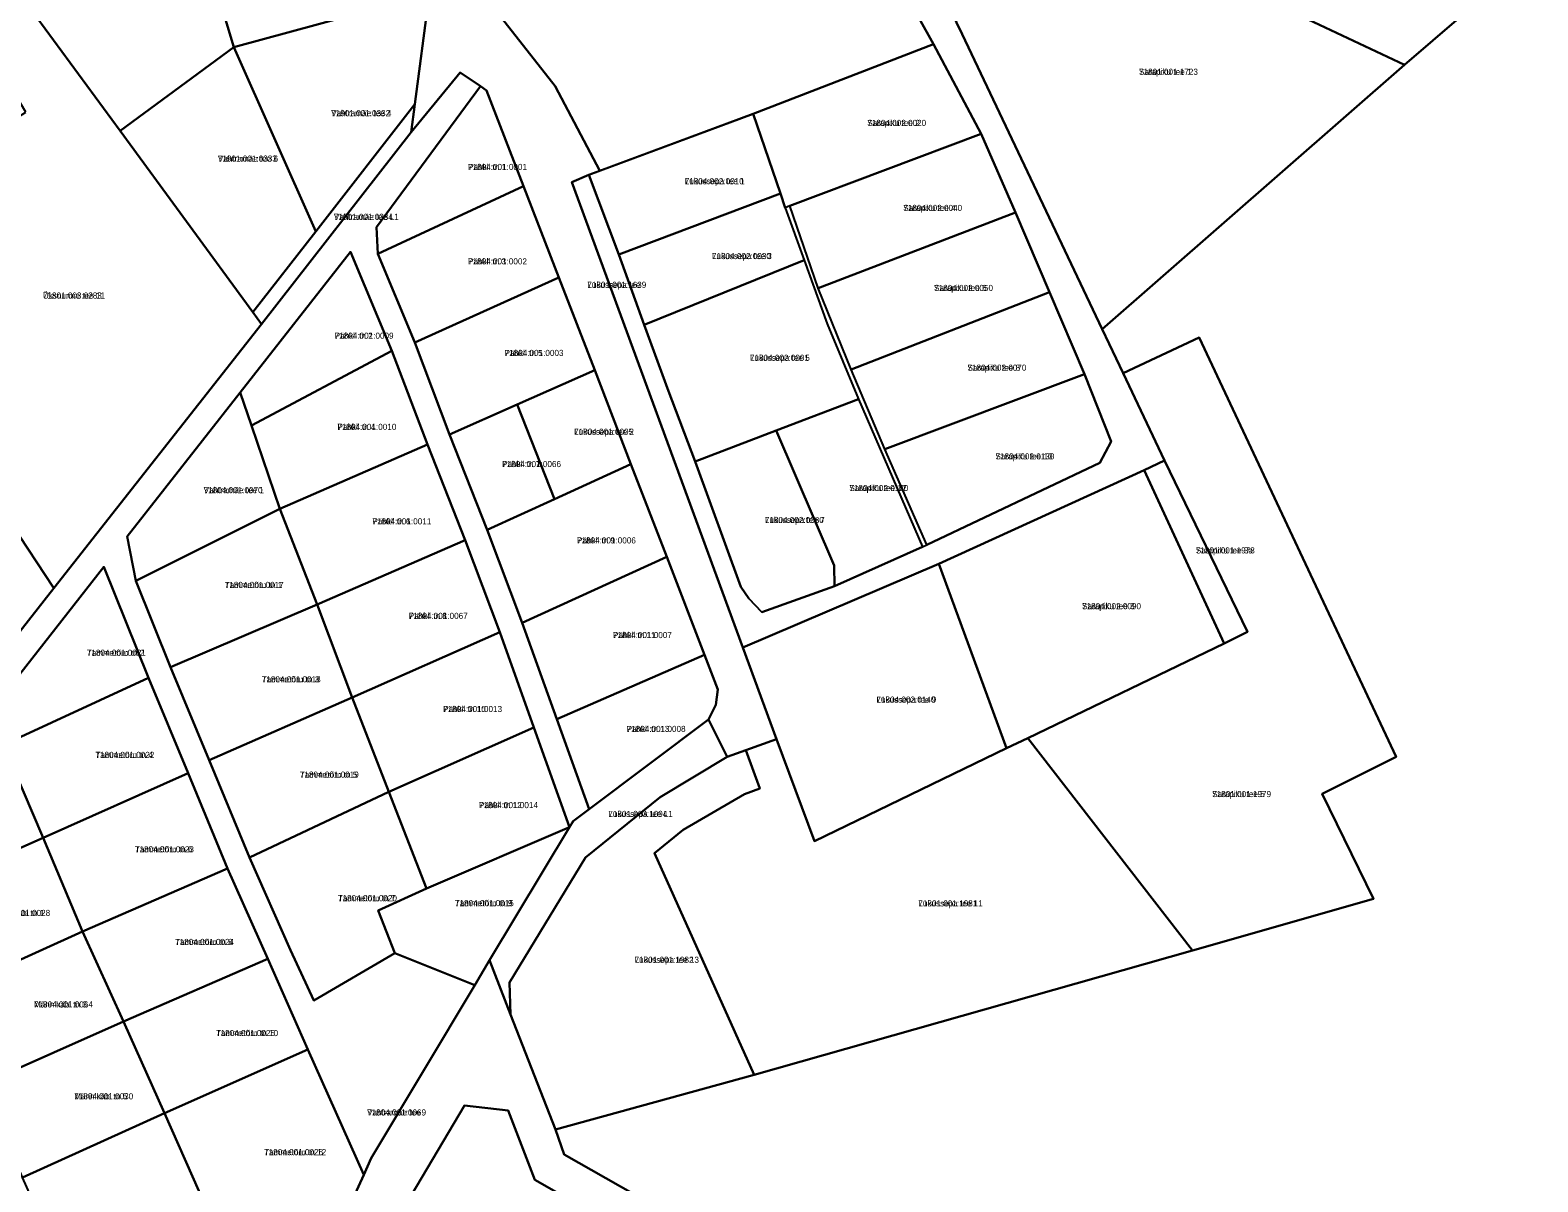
# Model space of a CAD drawing. Extents: x 529768 to 552006, y 6562269 to 6580975.
# Drawn here: x 536836 to 537206.9, y 6572299.8 to 6572583.3 of the extents above; entities that cross this region are included whole.
import ezdxf

# ---------------------------------------------------------------- set-up
doc = ezdxf.new("R2010")
doc.units = 0
for name, color, linetype in [('L_AADRESS', 7, 'Continuous'), ('PIIR', 7, 'Continuous'), ('TUNNUS', 7, 'Continuous')]:
    doc.layers.add(name, color=color, linetype=linetype)

msp = doc.modelspace()

# ---------------------------------------------------------------- linework, layer by layer
at = {"layer": 'PIIR'}
for points in [[(536949.22, 6572589.75), (536938.38, 6572627.92), (537020.07, 6572648.36), (537058.21, 6572579.8), (537013.87, 6572562.67), (536976.18, 6572548.65), (536965.17, 6572569.51)], [(537065.26, 6572582.3), (537043.48, 6572627.3), (537100.97, 6572644.38), (537109.91, 6572624.44), (537110.31, 6572623.51), (537120.04, 6572600.67), (537142.03, 6572589.8), (537174.13, 6572574.71), (537099.76, 6572509.71)], [(537142.03, 6572589.8), (537156.58, 6572600.06), (537198.96, 6572629.82), (537206.08, 6572619.65), (537208.84, 6572621.68), (537216.51, 6572611.21), (537174.13, 6572574.71)], [(536886.08, 6572579.04), (536877.27, 6572608.33), (536922.72, 6572621.78), (536933.5, 6572592.01)], [(536991.51, 6572292.84), (536967.39, 6572306.61), (536965.22, 6572312.7), (537014.09, 6572326.19), (537122.01, 6572356.76), (537166.48, 6572369.47), (537153.91, 6572395.36), (537172.12, 6572404.45), (537123.63, 6572507.61), (537104.93, 6572498.87), (537099.76, 6572509.71), (537174.13, 6572574.71), (537216.51, 6572611.21), (537216.46, 6572545.94), (537216.34, 6572355.99), (537216.73, 6572216.69), (537109.27, 6572167.25), (537012, 6572122.32), (537022.8, 6572262.32), (537006.74, 6572284.07)], [(536858.1, 6572558.51), (536831.48, 6572594.78), (536877.27, 6572608.33), (536886.08, 6572579.04)], [(536834.93, 6572563.1), (536817.36, 6572592.7), (536829.73, 6572597.13), (536831.48, 6572594.78), (536858.1, 6572558.51), (536890.77, 6572513.87), (536892.93, 6572510.9), (536841.8, 6572445.91), (536788.8, 6572526.33), (536785.28, 6572531.79), (536809.39, 6572546.99)], [(536906.23, 6572533.67), (536886.08, 6572579.04), (536933.5, 6572592.01), (536934, 6572590.65), (536930.65, 6572565.02)], [(536890.77, 6572513.87), (536858.1, 6572558.51), (536886.08, 6572579.04), (536906.23, 6572533.67)], [(537021.78, 6572539.56), (537020.56, 6572543.05), (537013.87, 6572562.67), (537058.21, 6572579.8), (537070.01, 6572557.76), (537022.89, 6572540.06)], [(536921.22, 6572534.76), (536946.76, 6572569.48), (536948.29, 6572568.44), (536957.4, 6572544.85), (536921.52, 6572528.19)], [(536892.93, 6572510.9), (536890.77, 6572513.87), (536906.23, 6572533.67), (536930.65, 6572565.02), (536929.76, 6572558.13)], [(536973.45, 6572547.63), (537013.87, 6572562.67), (537020.56, 6572543.05), (536980.78, 6572528.01)], [(537022.89, 6572540.06), (537070.01, 6572557.76), (537078.4, 6572538.42), (537029.86, 6572519.76)], [(536921.52, 6572528.19), (536957.4, 6572544.85), (536966.07, 6572522.39), (536930.63, 6572506.36)], [(536980.78, 6572528.01), (537020.56, 6572543.05), (537021.78, 6572539.56), (537026.4, 6572526.64), (536987.03, 6572510.76)], [(537029.86, 6572519.76), (537078.4, 6572538.42), (537086.76, 6572518.76), (537038.01, 6572499.72)], [(536805.18, 6572414.12), (536790.17, 6572434.86), (536787.8, 6572438.12), (536785.45, 6572441.33), (536744.06, 6572498.45), (536767.58, 6572513.11), (536788.8, 6572526.33), (536841.8, 6572445.91), (536812.33, 6572408.45)], [(536924.99, 6572504.32), (536890.43, 6572485.95), (536887.66, 6572494.07), (536914.8, 6572528.7)], [(536987.03, 6572510.76), (537026.4, 6572526.64), (537032.1, 6572510.95), (537039.8, 6572492.47), (537019.54, 6572484.75), (536999.6, 6572477.11), (536993, 6572494.42)], [(536930.63, 6572506.36), (536966.07, 6572522.39), (536974.88, 6572499.55), (536955.83, 6572491.13), (536939.19, 6572483.77)], [(537038.01, 6572499.72), (537086.76, 6572518.76), (537095.43, 6572498.62), (537046.28, 6572480.13)], [(537122.01, 6572356.76), (537081.48, 6572409.04), (537129.8, 6572432.35), (537135.47, 6572435.19), (537115.09, 6572477.35), (537104.93, 6572498.87), (537123.63, 6572507.61), (537172.12, 6572404.45), (537153.91, 6572395.36), (537166.48, 6572369.47)], [(536933.7, 6572481.32), (536897.43, 6572465.44), (536890.43, 6572485.95), (536924.99, 6572504.32)], [(536974.88, 6572499.55), (536983.81, 6572476.43), (536964.99, 6572467.85), (536955.83, 6572491.13)], [(537046.28, 6572480.13), (537095.43, 6572498.62), (537101.99, 6572482.04), (537099.13, 6572476.81), (537056.59, 6572456.63)], [(536887.66, 6572494.07), (536890.43, 6572485.95), (536897.43, 6572465.44), (536861.97, 6572447.7), (536859.88, 6572458.61)], [(537033.82, 6572451.53), (537019.54, 6572484.75), (537039.8, 6572492.47), (537055.53, 6572456.12), (537033.9, 6572446.43)], [(536939.19, 6572483.77), (536955.83, 6572491.13), (536964.99, 6572467.85), (536948.41, 6572460.3)], [(537010.87, 6572446.3), (536999.6, 6572477.11), (537019.54, 6572484.75), (537033.82, 6572451.53), (537033.9, 6572446.43), (537016.04, 6572440.01), (537012.84, 6572443.42)], [(536942.97, 6572457.73), (536906.6, 6572441.95), (536897.43, 6572465.44), (536933.7, 6572481.32)], [(537129.8, 6572432.35), (537110.1, 6572474.98), (537115.09, 6572477.35), (537135.47, 6572435.19)], [(536948.41, 6572460.3), (536964.99, 6572467.85), (536983.81, 6572476.43), (536992.61, 6572453.63), (536957.07, 6572437.44)], [(537076.24, 6572406.53), (537059.57, 6572451.9), (537110.1, 6572474.98), (537129.8, 6572432.35), (537081.48, 6572409.04)], [(536861.97, 6572447.7), (536897.43, 6572465.44), (536906.6, 6572441.95), (536870.51, 6572426.53)], [(536906.6, 6572441.95), (536942.97, 6572457.73), (536951.55, 6572435.09), (536915.24, 6572419)], [(536854.08, 6572451.22), (536865.12, 6572423.86), (536829.4, 6572407.37), (536826, 6572415.38)], [(536957.07, 6572437.44), (536992.61, 6572453.63), (537001.9, 6572429.55), (536965.55, 6572413.68)], [(537011.34, 6572431.3), (537059.57, 6572451.9), (537076.24, 6572406.53), (537028.96, 6572383.64), (537019.58, 6572408.8)], [(536870.51, 6572426.53), (536906.6, 6572441.95), (536915.24, 6572419), (536880.01, 6572403.58)], [(536959.92, 6572411.62), (536924.25, 6572395.8), (536915.24, 6572419), (536951.55, 6572435.09)], [(537001.9, 6572429.55), (537005.21, 6572420.98), (537004.7, 6572417.23), (537002.89, 6572413.62), (536973.5, 6572391.55), (536965.55, 6572413.68)], [(536874.83, 6572400.4), (536839.14, 6572384.47), (536829.4, 6572407.37), (536865.12, 6572423.86)], [(536924.25, 6572395.8), (536889.92, 6572379.62), (536880.01, 6572403.58), (536915.24, 6572419)], [(536798.6, 6572380.42), (536826, 6572415.38), (536829.4, 6572407.37), (536839.14, 6572384.47), (536803.79, 6572368.86)], [(536968.71, 6572387.16), (536933.5, 6572371.99), (536924.25, 6572395.8), (536959.92, 6572411.62)], [(537002.89, 6572413.62), (537007.47, 6572404.47), (536991, 6572394.54), (536972.65, 6572379.64), (536953.93, 6572348.92), (536954.19, 6572340.99), (536949.01, 6572354.41), (536968.71, 6572387.16), (536969.57, 6572388.6), (536973.5, 6572391.55)], [(537014.09, 6572326.19), (536989.57, 6572380.69), (536996.65, 6572386.46), (537011.73, 6572395.28), (537015.48, 6572396.66), (537012.1, 6572406.09), (537019.58, 6572408.8), (537028.96, 6572383.64), (537076.24, 6572406.53), (537081.48, 6572409.04), (537122.01, 6572356.76)], [(536954.19, 6572340.99), (536953.93, 6572348.92), (536972.65, 6572379.64), (536991, 6572394.54), (537007.47, 6572404.47), (537012.1, 6572406.09), (537015.48, 6572396.66), (537011.73, 6572395.28), (536996.65, 6572386.46), (536989.57, 6572380.69), (537014.09, 6572326.19), (536965.22, 6572312.7)], [(536884.55, 6572376.92), (536848.87, 6572361.46), (536839.14, 6572384.47), (536874.83, 6572400.4)], [(536900.03, 6572356.87), (536889.92, 6572379.62), (536924.25, 6572395.8), (536933.5, 6572371.99), (536921.59, 6572366.61), (536925.7, 6572356.09), (536905.78, 6572344.43)], [(536803.79, 6572368.86), (536839.14, 6572384.47), (536848.87, 6572361.46), (536814.99, 6572346.08)], [(536933.5, 6572371.99), (536968.71, 6572387.16), (536949.01, 6572354.41), (536945.38, 6572348.2), (536925.7, 6572356.09), (536921.59, 6572366.61)], [(536894.42, 6572354.72), (536858.92, 6572339.34), (536848.87, 6572361.46), (536884.55, 6572376.92)], [(536848.87, 6572361.46), (536858.92, 6572339.34), (536824.55, 6572324.03), (536814.99, 6572346.08)], [(536904.33, 6572332.43), (536869.04, 6572316.71), (536858.92, 6572339.34), (536894.42, 6572354.72)], [(536824.55, 6572324.03), (536858.92, 6572339.34), (536869.04, 6572316.71), (536834.07, 6572300.95)], [(536918.05, 6572301.57), (536903, 6572268.54), (536887.5, 6572295.82), (536879.32, 6572293.35), (536869.04, 6572316.71), (536904.33, 6572332.43)], [(536925.79, 6572289.85), (536942.85, 6572318.65), (536953.61, 6572317.39), (536960.14, 6572300.36), (536987.04, 6572285.02), (536973.95, 6572262.09)], [(536834.07, 6572300.95), (536869.04, 6572316.71), (536879.32, 6572293.35), (536880.16, 6572291.53), (536844.73, 6572277.11)]]:
    msp.add_lwpolyline(points, close=True, dxfattribs=at)
for points in [[(537043.48, 6572627.3), (537065.26, 6572582.3), (537099.76, 6572509.71), (537104.93, 6572498.87), (537115.09, 6572477.35), (537110.1, 6572474.98), (537059.57, 6572451.9), (537011.34, 6572431.3), (536969.25, 6572545.84), (536973.45, 6572547.63), (536980.78, 6572528.01), (536987.03, 6572510.76), (536993, 6572494.42), (536999.6, 6572477.11), (537010.87, 6572446.3), (537012.84, 6572443.42), (537016.04, 6572440.01), (537033.9, 6572446.43), (537055.53, 6572456.12), (537056.59, 6572456.63), (537099.13, 6572476.81), (537101.99, 6572482.04), (537095.43, 6572498.62), (537086.76, 6572518.76), (537078.4, 6572538.42), (537070.01, 6572557.76), (537058.21, 6572579.8), (537020.07, 6572648.36)], [(536949.22, 6572589.75), (536965.17, 6572569.51), (536976.18, 6572548.65), (536973.45, 6572547.63), (536969.25, 6572545.84), (537011.34, 6572431.3), (537019.58, 6572408.8), (537012.1, 6572406.09), (537007.47, 6572404.47), (537002.89, 6572413.62), (537004.7, 6572417.23), (537005.21, 6572420.98), (537001.9, 6572429.55), (536992.61, 6572453.63), (536983.81, 6572476.43), (536974.88, 6572499.55), (536966.07, 6572522.39), (536957.4, 6572544.85), (536948.29, 6572568.44), (536946.76, 6572569.48), (536941.79, 6572572.86), (536929.76, 6572558.13), (536930.65, 6572565.02), (536934, 6572590.65)], [(536812.33, 6572408.45), (536841.8, 6572445.91), (536892.93, 6572510.9), (536929.76, 6572558.13), (536941.79, 6572572.86), (536946.76, 6572569.48), (536921.22, 6572534.76), (536921.52, 6572528.19), (536930.63, 6572506.36), (536939.19, 6572483.77), (536948.41, 6572460.3), (536957.07, 6572437.44), (536965.55, 6572413.68), (536973.5, 6572391.55), (536969.57, 6572388.6), (536968.71, 6572387.16), (536959.92, 6572411.62), (536951.55, 6572435.09), (536942.97, 6572457.73), (536933.7, 6572481.32), (536924.99, 6572504.32), (536914.8, 6572528.7), (536887.66, 6572494.07), (536859.88, 6572458.61), (536861.97, 6572447.7), (536870.51, 6572426.53), (536880.01, 6572403.58), (536889.92, 6572379.62), (536900.03, 6572356.87), (536905.78, 6572344.43), (536925.7, 6572356.09), (536945.38, 6572348.2), (536919.9, 6572305.63), (536918.05, 6572301.57), (536904.33, 6572332.43), (536894.42, 6572354.72), (536884.55, 6572376.92), (536874.83, 6572400.4), (536865.12, 6572423.86), (536854.08, 6572451.22), (536826, 6572415.38)], [(536903, 6572268.54), (536918.05, 6572301.57), (536919.9, 6572305.63), (536945.38, 6572348.2), (536949.01, 6572354.41), (536954.19, 6572340.99), (536965.22, 6572312.7), (536967.39, 6572306.61), (536991.51, 6572292.84)], [(536987.04, 6572285.02), (536960.14, 6572300.36), (536953.61, 6572317.39), (536942.85, 6572318.65), (536925.79, 6572289.85)]]:
    msp.add_lwpolyline(points, dxfattribs=at)

# ---------------------------------------------------------------- texts
at = {"layer": 'L_AADRESS'}
for s, p in [('Sarapiku tee 1', (537108.8, 6572572.26)), ('Vahtramäe tee 4', (536910.04, 6572562.08)), ('Sarapiku tee 2', (537041.94, 6572559.68)), ('Vahtramäe tee 6', (536882.16, 6572550.9)), ('Pähkli tn 1', (536943.72, 6572548.84)), ('Lukussepa tee 1', (536997.04, 6572545.34)), ('Sarapiku tee 4', (537050.79, 6572538.76)), ('Vahtramäe tee L1', (536910.71, 6572536.56)), ('Pähkli tn 3', (536943.71, 6572525.61)), ('Lukussepa tee 3', (537003.74, 6572526.91)), ('Lukussepa tee', (536973.07, 6572519.84)), ('Üksnurme tee 11', (536839.11, 6572517.2)), ('Sarapiku tee 6', (537058.38, 6572519.07)), ('Pähkli tn 2', (536910.89, 6572507.32)), ('Pähkli tn 5', (536952.7, 6572503.08)), ('Lukussepa tee 5', (537013.08, 6572501.88)), ('Sarapiku tee 8', (537066.6, 6572499.45)), ('Pähkli tn 4', (536911.57, 6572484.88)), ('Lukussepa tee 2', (536969.82, 6572483.68)), ('Pähkli tn 7', (536952.09, 6572475.73)), ('Sarapiku tee 10', (537073.48, 6572477.62)), ('Vahtramäe tee 1', (536878.66, 6572469.31)), ('Sarapiku tee 12', (537037.54, 6572469.83)), ('Pähkli tn 6', (536920.18, 6572461.63)), ('Lukussepa tee 7', (537016.75, 6572461.97)), ('Pähkli tn 9', (536970.51, 6572456.94)), ('Sarapiku tee 3a', (537122.79, 6572454.48)), ('Tammetõru tn 1', (536883.84, 6572445.99)), ('Pähkli tn 8', (536929.13, 6572438.37)), ('Sarapiku tee 3', (537094.79, 6572440.76)), ('Pähkli tn 11', (536979.37, 6572433.65)), ('Tammetõru tn 2', (536849.91, 6572429.29)), ('Tammetõru tn 3', (536892.95, 6572422.76)), ('Lukussepa tee 9', (537044.2, 6572417.77)), ('Pähkli tn 10', (536937.59, 6572415.45)), ('Pähkli tn 13', (536982.74, 6572410.55)), ('Tammetõru tn 4', (536852.02, 6572404.16)), ('Tammetõru tn 5', (536902.33, 6572399.31)), ('Sarapiku tee 5', (537126.8, 6572394.52)), ('Pähkli tn 12', (536946.42, 6572391.8)), ('Lukussepa tee L1', (536978.24, 6572389.64)), ('Tammetõru tn 6', (536861.76, 6572380.93)), ('Tammetõru tn 7', (536911.71, 6572368.9)), ('Tammetõru tn 9', (536940.48, 6572367.68)), ('Männikäbi tn 1', (536826.4, 6572365.27)), ('Lukussepa tee 11', (537054.52, 6572367.62)), ('Tammetõru tn 8', (536871.64, 6572358.13)), ('Lukussepa tee 13', (536984.7, 6572353.75)), ('Männikäbi tn 3', (536836.9, 6572342.75)), ('Tammetõru tn 10', (536881.71, 6572335.71)), ('Männikäbi tn 5', (536846.83, 6572320.15)), ('Vahtramäe tee', (536918.88, 6572316.17)), ('Tammetõru tn 12', (536893.54, 6572306.4))]:
    msp.add_text(s, height=1.5, dxfattribs=at).set_placement(p)
at = {"layer": 'TUNNUS'}
for s, p in [('71801:001:1723', (537108.8, 6572572.26)), ('71901:001:0332', (536910.04, 6572562.08)), ('71804:002:0020', (537041.94, 6572559.68)), ('71901:001:0333', (536882.16, 6572550.9)), ('71804:001:0001', (536943.72, 6572548.84)), ('71804:002:0010', (536997.04, 6572545.34)), ('71804:002:0040', (537050.79, 6572538.76)), ('71901:001:0334', (536910.71, 6572536.56)), ('71804:001:0002', (536943.71, 6572525.61)), ('71804:002:0030', (537003.74, 6572526.91)), ('71801:001:1639', (536973.07, 6572519.84)), ('71801:003:0283', (536839.11, 6572517.2)), ('71804:002:0050', (537058.38, 6572519.07)), ('71804:001:0009', (536910.89, 6572507.32)), ('71804:001:0003', (536952.7, 6572503.08)), ('71804:002:0001', (537013.08, 6572501.88)), ('71804:002:0070', (537066.6, 6572499.45)), ('71804:001:0010', (536911.57, 6572484.88)), ('71804:001:0005', (536969.82, 6572483.68)), ('71804:001:0066', (536952.09, 6572475.73)), ('71804:002:0130', (537073.48, 6572477.62)), ('71804:001:0070', (536878.66, 6572469.31)), ('71804:002:0120', (537037.54, 6572469.83)), ('71804:001:0011', (536920.18, 6572461.63)), ('71804:002:0080', (537016.75, 6572461.97)), ('71804:001:0006', (536970.51, 6572456.94)), ('71801:001:1978', (537122.79, 6572454.48)), ('71804:001:0017', (536883.84, 6572445.99)), ('71804:001:0067', (536929.13, 6572438.37)), ('71804:002:0090', (537094.79, 6572440.76)), ('71804:001:0007', (536979.37, 6572433.65)), ('71804:001:0021', (536849.91, 6572429.29)), ('71804:001:0018', (536892.95, 6572422.76)), ('71804:002:0140', (537044.2, 6572417.77)), ('71804:001:0013', (536937.59, 6572415.45)), ('71804:001:0008', (536982.74, 6572410.55)), ('71804:001:0022', (536852.02, 6572404.16)), ('71804:001:0019', (536902.33, 6572399.31)), ('71801:001:1979', (537126.8, 6572394.52)), ('71804:001:0014', (536946.42, 6572391.8)), ('71801:003:1094', (536978.24, 6572389.64)), ('71804:001:0023', (536861.76, 6572380.93)), ('71804:001:0020', (536911.71, 6572368.9)), ('71804:001:0028', (536826.4, 6572365.27)), ('71804:001:0015', (536940.48, 6572367.68)), ('71801:001:1981', (537054.52, 6572367.62)), ('71804:001:0024', (536871.64, 6572358.13)), ('71801:001:1982', (536984.7, 6572353.75)), ('71804:001:0064', (536836.9, 6572342.75)), ('71804:001:0025', (536881.71, 6572335.71)), ('71804:001:0030', (536846.83, 6572320.15)), ('71804:001:0069', (536918.88, 6572316.17)), ('71804:001:0026', (536893.54, 6572306.4))]:
    msp.add_text(s, height=1.5, dxfattribs=at).set_placement(p)

doc.saveas('drawing.dxf')
